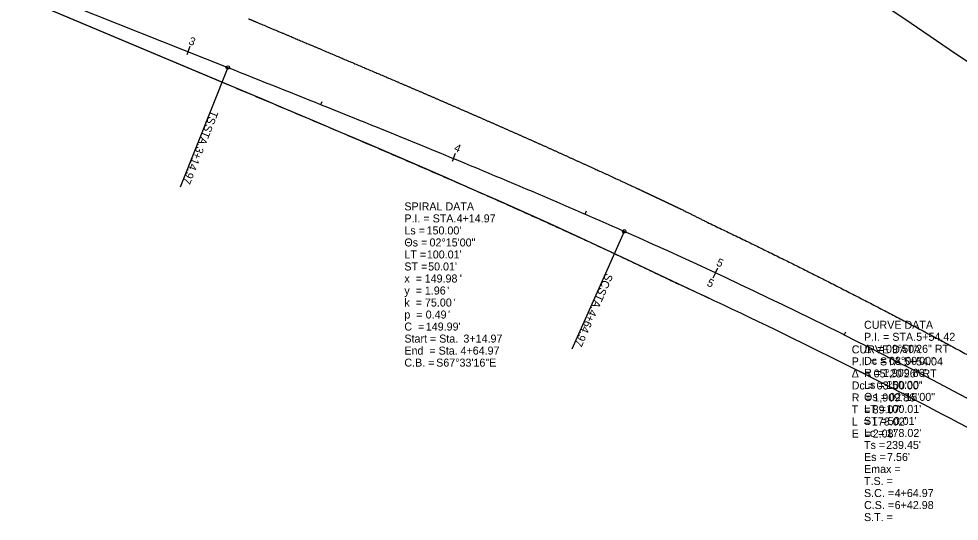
# Model space of a CAD drawing. Extents: x 1323137 to 1326838, y 458936 to 461644.
# Drawn here: x 1325220.9 to 1325549.7, y 459598.5 to 459774 of the extents above; entities that cross this region are included whole.
import ezdxf

# ---------------------------------------------------------------- set-up
doc = ezdxf.new("R2010")
doc.units = 0
for name, color, linetype in [('Default', 7, 'Continuous'), ('DT_P_Tie', 7, 'Continuous'), ('MD_P_ACB_B', 7, 'Continuous'), ('MD_P_ACSC_B', 7, 'Continuous'), ('MD_P_AGB_B', 7, 'Continuous'), ('MD_P_AGB_T', 7, 'Continuous'), ('PV_P_Shoulder', 7, 'Continuous'), ('SG_P_Conduit', 7, 'Continuous'), ('SG_P_Mast_Arm', 7, 'Continuous'), ('SN_P_Signs', 7, 'Continuous')]:
    doc.layers.add(name, color=color, linetype=linetype)

msp = doc.modelspace()

# ---------------------------------------------------------------- linework, layer by layer
at = {"layer": 'Default'}
msp.add_line((1325001.32, 459873.45), (1325293.97, 459757.01), dxfattribs=at)
for points in [[(1325451.7, 459681.24), (1325442.79, 459685.53), (1325433.79, 459689.8), (1325424.78, 459694.02), (1325415.73, 459698.2), (1325406.67, 459702.34), (1325397.58, 459706.44), (1325388.48, 459710.51), (1325379.35, 459714.54), (1325370.21, 459718.54), (1325361.06, 459722.52), (1325351.89, 459726.48), (1325342.71, 459730.41), (1325333.52, 459734.33), (1325324.32, 459738.24), (1325315.11, 459742.13), (1325305.9, 459746.02), (1325296.69, 459749.9), (1325222.91, 459780.98), (1325213.53, 459784.78), (1325076.26, 459836.24)], [(1325586.72, 459613.4), (1325584.96, 459614.34), (1325576.17, 459619), (1325567.35, 459623.63), (1325558.51, 459628.2), (1325549.7, 459632.7)]]:
    msp.add_lwpolyline(points, dxfattribs=at)
for centre, radius, start, end in [((1332431.06, 469929.07), 12277.67, 232.043309, 236.873031), ((1324657.44, 457954.27), 1909.86, 60.71386, 66.05442), ((1324657.44, 457954.27), 1900.86, 62.00488, 65.30182)]:
    msp.add_arc(centre, radius, start, end, dxfattribs=at)
msp.add_open_spline([(1325293.97, 459757.01), (1325305.58, 459752.39), (1325328.82, 459743.16), (1325363.59, 459729.11), (1325398.23, 459714.75), (1325421.17, 459704.82), (1325432.6, 459699.75)], degree=3, dxfattribs=at)
at = {"layer": 'DT_P_Tie'}
for p, q in [((1325038.48, 459858.66), (1325291.94, 459751.9)), ((1325038.48, 459858.66), (1325291.94, 459751.9)), ((1325439.3, 459713.73), (1325439.31, 459713.72)), ((1325439.3, 459713.73), (1325439.31, 459713.72)), ((1325439.31, 459713.72), (1325439.33, 459713.71)), ((1325439.31, 459713.72), (1325439.33, 459713.71)), ((1325462.05, 459702.73), (1325462.14, 459702.69)), ((1325462.05, 459702.73), (1325462.14, 459702.69))]:
    msp.add_line(p, q, dxfattribs=at)
msp.add_arc((1324657.44, 457954.27), 1900.86, 62.00341, 65.30341, dxfattribs=at)
msp.add_arc((1324657.44, 457954.27), 1900.86, 62.00341, 65.30341, dxfattribs=at)
for points, degree in [([(1325301.25, 459774.02), (1325302.56, 459773.47), (1325307.09, 459771.56), (1325315.35, 459768.09), (1325321.89, 459765.32), (1325328.9, 459762.36), (1325335.79, 459759.44), (1325342.71, 459756.5), (1325349.62, 459753.56), (1325356.54, 459750.6), (1325363.46, 459747.63), (1325370.37, 459744.64), (1325377.28, 459741.64), (1325384.2, 459738.63), (1325391.1, 459735.59), (1325398.01, 459732.54), (1325404.92, 459729.46), (1325411.78, 459726.37), (1325418.78, 459723.2), (1325425.29, 459720.23), (1325433.53, 459716.42), (1325438.02, 459714.32), (1325439.3, 459713.73)], 2), ([(1325301.25, 459774.02), (1325302.56, 459773.47), (1325307.09, 459771.56), (1325315.35, 459768.09), (1325321.89, 459765.32), (1325328.9, 459762.36), (1325335.79, 459759.44), (1325342.71, 459756.5), (1325349.62, 459753.56), (1325356.54, 459750.6), (1325363.46, 459747.63), (1325370.37, 459744.64), (1325377.28, 459741.64), (1325384.2, 459738.63), (1325391.1, 459735.59), (1325398.01, 459732.54), (1325404.92, 459729.46), (1325411.78, 459726.37), (1325418.78, 459723.2), (1325425.29, 459720.23), (1325433.53, 459716.42), (1325438.02, 459714.32), (1325439.3, 459713.73)], 2), ([(1325291.94, 459751.9), (1325294.24, 459750.93), (1325298.85, 459748.99), (1325305.76, 459746.08), (1325312.67, 459743.17), (1325319.58, 459740.25), (1325326.48, 459737.32), (1325333.38, 459734.39), (1325340.27, 459731.46), (1325347.16, 459728.51), (1325354.04, 459725.55), (1325360.91, 459722.59), (1325367.78, 459719.6), (1325374.64, 459716.61), (1325381.49, 459713.6), (1325388.34, 459710.57), (1325395.17, 459707.53), (1325401.99, 459704.46), (1325408.8, 459701.38), (1325415.59, 459698.27), (1325422.38, 459695.14), (1325426.89, 459693.03), (1325429.15, 459691.98)], 3), ([(1325291.94, 459751.9), (1325294.24, 459750.93), (1325298.85, 459748.99), (1325305.76, 459746.08), (1325312.67, 459743.17), (1325319.58, 459740.25), (1325326.48, 459737.32), (1325333.38, 459734.39), (1325340.27, 459731.46), (1325347.16, 459728.51), (1325354.04, 459725.55), (1325360.91, 459722.59), (1325367.78, 459719.6), (1325374.64, 459716.61), (1325381.49, 459713.6), (1325388.34, 459710.57), (1325395.17, 459707.53), (1325401.99, 459704.46), (1325408.8, 459701.38), (1325415.59, 459698.27), (1325422.38, 459695.14), (1325426.89, 459693.03), (1325429.15, 459691.98)], 3), ([(1325439.33, 459713.71), (1325439.54, 459713.61), (1325440.26, 459713.28), (1325441.59, 459712.65), (1325442.64, 459712.16), (1325443.77, 459711.63), (1325444.88, 459711.1), (1325445.99, 459710.58), (1325447.1, 459710.05), (1325448.2, 459709.53), (1325449.32, 459709), (1325450.37, 459708.5), (1325451.7, 459707.87), (1325452.42, 459707.52), (1325452.63, 459707.42)], 2), ([(1325439.33, 459713.71), (1325439.54, 459713.61), (1325440.26, 459713.28), (1325441.59, 459712.65), (1325442.64, 459712.16), (1325443.77, 459711.63), (1325444.88, 459711.1), (1325445.99, 459710.58), (1325447.1, 459710.05), (1325448.2, 459709.53), (1325449.32, 459709), (1325450.37, 459708.5), (1325451.7, 459707.87), (1325452.42, 459707.52), (1325452.63, 459707.42)], 2), ([(1325452.38, 459707.54), (1325452.59, 459707.44), (1325453.29, 459707.09), (1325454.58, 459706.45), (1325455.6, 459705.95), (1325456.69, 459705.41), (1325457.75, 459704.88), (1325458.84, 459704.33), (1325459.86, 459703.83), (1325461.15, 459703.18), (1325461.85, 459702.83), (1325462.05, 459702.73)], 3), ([(1325452.38, 459707.54), (1325452.59, 459707.44), (1325453.29, 459707.09), (1325454.58, 459706.45), (1325455.6, 459705.95), (1325456.69, 459705.41), (1325457.75, 459704.88), (1325458.84, 459704.33), (1325459.86, 459703.83), (1325461.15, 459703.18), (1325461.85, 459702.83), (1325462.05, 459702.73)], 3), ([(1325461.62, 459702.94), (1325463.28, 459702.14), (1325466.62, 459700.55), (1325471.61, 459698.15), (1325476.6, 459695.73), (1325481.58, 459693.3), (1325486.56, 459690.85), (1325491.52, 459688.39), (1325496.48, 459685.91), (1325501.43, 459683.42), (1325506.37, 459680.92), (1325511.31, 459678.4), (1325516.24, 459675.87), (1325521.16, 459673.33), (1325526.08, 459670.77), (1325530.98, 459668.19), (1325535.88, 459665.61), (1325540.77, 459663), (1325545.66, 459660.39), (1325550.53, 459657.76), (1325555.4, 459655.12), (1325558.64, 459653.34), (1325560.26, 459652.46)], 3), ([(1325461.62, 459702.94), (1325463.28, 459702.14), (1325466.62, 459700.55), (1325471.61, 459698.15), (1325476.6, 459695.73), (1325481.58, 459693.3), (1325486.56, 459690.85), (1325491.52, 459688.39), (1325496.48, 459685.91), (1325501.43, 459683.42), (1325506.37, 459680.92), (1325511.31, 459678.4), (1325516.24, 459675.87), (1325521.16, 459673.33), (1325526.08, 459670.77), (1325530.98, 459668.19), (1325535.88, 459665.61), (1325540.77, 459663), (1325545.66, 459660.39), (1325550.53, 459657.76), (1325555.4, 459655.12), (1325558.64, 459653.34), (1325560.26, 459652.46)], 3), ([(1325429.15, 459691.98), (1325429.52, 459691.8), (1325430.28, 459691.45), (1325431.4, 459690.92), (1325432.53, 459690.39), (1325433.66, 459689.86), (1325434.79, 459689.33), (1325435.91, 459688.79), (1325437.04, 459688.26), (1325438.17, 459687.73), (1325439.29, 459687.19), (1325440.42, 459686.66), (1325441.54, 459686.12), (1325442.67, 459685.58), (1325443.79, 459685.05), (1325444.91, 459684.51), (1325446.04, 459683.97), (1325447.16, 459683.43), (1325448.28, 459682.89), (1325449.4, 459682.35), (1325450.53, 459681.8), (1325451.27, 459681.44), (1325451.65, 459681.26)], 3), ([(1325429.15, 459691.98), (1325429.52, 459691.8), (1325430.28, 459691.45), (1325431.4, 459690.92), (1325432.53, 459690.39), (1325433.66, 459689.86), (1325434.79, 459689.33), (1325435.91, 459688.79), (1325437.04, 459688.26), (1325438.17, 459687.73), (1325439.29, 459687.19), (1325440.42, 459686.66), (1325441.54, 459686.12), (1325442.67, 459685.58), (1325443.79, 459685.05), (1325444.91, 459684.51), (1325446.04, 459683.97), (1325447.16, 459683.43), (1325448.28, 459682.89), (1325449.4, 459682.35), (1325450.53, 459681.8), (1325451.27, 459681.44), (1325451.65, 459681.26)], 3)]:
    msp.add_open_spline(points, degree=degree, dxfattribs=at)
at = {"layer": 'MD_P_ACB_B'}
for p, q in [((1325293.97, 459757.01), (1325277.33, 459715.2)), ((1325432.6, 459699.75), (1325414.33, 459658.62))]:
    msp.add_line(p, q, dxfattribs=at)
for centre in [(1325293.97, 459757.01), (1325432.6, 459699.75)]:
    msp.add_circle(centre, 0.6, dxfattribs=at)
at = {"layer": 'MD_P_ACSC_B'}
for p, q in [((1325293.97, 459757.01), (1325277.33, 459715.2)), ((1325432.6, 459699.75), (1325414.33, 459658.62))]:
    msp.add_line(p, q, dxfattribs=at)
for centre in [(1325293.97, 459757.01), (1325432.6, 459699.75)]:
    msp.add_circle(centre, 0.6, dxfattribs=at)
at = {"layer": 'PV_P_Shoulder'}
for p, q in [((1325280.06, 459762.55), (1325279.62, 459761.43)), ((1325372.85, 459725.25), (1325372.39, 459724.14)), ((1325464.48, 459685.24), (1325463.64, 459683.42))]:
    msp.add_line(p, q, dxfattribs=at)
at = {"layer": 'SG_P_Conduit'}
msp.add_line((1325001.32, 459873.45), (1325293.97, 459757.01), dxfattribs=at)
msp.add_arc((1324657.44, 457954.27), 1909.86, 60.71386, 66.05442, dxfattribs=at)
msp.add_open_spline([(1325293.97, 459757.01), (1325305.58, 459752.39), (1325328.82, 459743.16), (1325363.59, 459729.11), (1325398.23, 459714.75), (1325421.17, 459704.82), (1325432.6, 459699.75)], degree=3, dxfattribs=at)
at = {"layer": 'SG_P_Mast_Arm'}
for p, q in [((1325280.06, 459762.55), (1325280.8, 459764.41)), ((1325326.51, 459744.04), (1325326.96, 459745.15)), ((1325372.85, 459725.25), (1325373.61, 459727.1)), ((1325418.9, 459705.77), (1325419.37, 459706.87)), ((1325464.48, 459685.24), (1325465.33, 459687.05)), ((1325509.52, 459663.52), (1325510.05, 459664.59))]:
    msp.add_line(p, q, dxfattribs=at)
at = {"layer": 'SN_P_Signs'}
msp.add_line((1325001.32, 459873.45), (1325293.97, 459757.01), dxfattribs=at)
for centre, radius, start, end in [((1332431.06, 469929.07), 12277.67, 232.043309, 236.873031), ((1324657.44, 457954.27), 1909.86, 60.71386, 66.05442)]:
    msp.add_arc(centre, radius, start, end, dxfattribs=at)
msp.add_open_spline([(1325293.97, 459757.01), (1325305.58, 459752.39), (1325328.82, 459743.16), (1325363.59, 459729.11), (1325398.23, 459714.75), (1325421.17, 459704.82), (1325432.6, 459699.75)], degree=3, dxfattribs=at)

# ---------------------------------------------------------------- texts
at = {"layer": 'MD_P_ACB_B'}
for s, rotation, p in [('TS', 248.3044, (1325288.13, 459742.23)), (' STA. ', 248.3044, (1325286.6, 459738.38)), ('3+14.97', 248.3044, (1325283.11, 459729.6)), ('SC', 246.0544, (1325426.22, 459685.28)), (' STA. ', 246.0544, (1325424.47, 459681.34)), ('4+64.97', 246.0544, (1325420.63, 459672.71))]:
    msp.add_text(s, height=2.8, rotation=rotation, dxfattribs=at).set_placement(p)
at = {"layer": 'MD_P_ACSC_B'}
for s, rotation, p in [('TS', 248.3044, (1325288.13, 459742.23)), (' STA. ', 248.3044, (1325286.6, 459738.38)), ('3+14.97', 248.3044, (1325283.11, 459729.6)), ('SC', 246.0544, (1325426.22, 459685.28)), (' STA. ', 246.0544, (1325424.47, 459681.34)), ('4+64.97', 246.0544, (1325420.63, 459672.71))]:
    msp.add_text(s, height=2.8, rotation=rotation, dxfattribs=at).set_placement(p)
at = {"layer": 'MD_P_AGB_B'}
for s, p in [('SPIRAL DATA', (1325355.71, 459707.07)), ('P.I. = STA. ', (1325355.71, 459702.87)), ('4+14.97', (1325373.97, 459702.87)), ('Ls = ', (1325355.71, 459698.67)), ("150.00'", (1325363.47, 459698.67)), ('Θs = ', (1325355.71, 459694.47)), ('02°15\'00"', (1325364.51, 459694.47)), ('LT = ', (1325355.71, 459690.27)), ("100.01'", (1325363.56, 459690.27)), ('ST = ', (1325355.71, 459686.07)), ("50.01'", (1325364.02, 459686.07)), ('x  = ', (1325355.71, 459681.87)), ('149.98', (1325362.81, 459681.87)), ("'", (1325375.09, 459681.87)), ('y  = ', (1325355.71, 459677.67)), ('1.96', (1325362.87, 459677.67)), ("'", (1325370.69, 459677.67)), ('k  = ', (1325355.71, 459673.47)), ('75.00', (1325362.9, 459673.47)), ("'", (1325372.95, 459673.47)), ('p  = ', (1325355.71, 459669.27)), ('0.49', (1325363.16, 459669.27)), ("'", (1325370.98, 459669.27)), ('C  = ', (1325355.71, 459665.07)), ("149.99'", (1325363.2, 459665.07)), ('CURVE DATA', (1325516.46, 459665.69)), ('Start = Sta. ', (1325355.71, 459660.87)), ('3+14.97', (1325376.36, 459660.87)), ('P.I. = STA. ', (1325516.46, 459661.49)), ('5+54.42', (1325534.73, 459661.49)), ('End  = Sta. ', (1325355.71, 459656.67)), ('4+64.97', (1325375.34, 459656.67)), ('CURVE DATA', (1325512.15, 459657.09)), ('Δ  = ', (1325516.46, 459657.29)), ('09°50\'26" RT', (1325524.14, 459657.29)), ('C.B. = ', (1325355.71, 459652.47)), ('S67°33\'16"E', (1325366.83, 459652.47)), ('P.I. = STA. ', (1325512.15, 459652.89)), ('Dc = ', (1325516.46, 459653.09)), ('03°00\'00"', (1325525.2, 459653.09)), ('5+54.04', (1325530.41, 459652.89)), ('Δ  = ', (1325512.15, 459648.69)), ('R = ', (1325516.46, 459648.89)), ('05°20\'26" RT', (1325519.82, 459648.69)), ("1,909.86'", (1325523.05, 459648.89)), ('Dc = ', (1325512.15, 459644.49)), ('Ls = ', (1325516.46, 459644.69)), ('03°00\'00"', (1325520.88, 459644.49)), ("150.00'", (1325524.22, 459644.69)), ('R  = ', (1325512.15, 459640.29)), ('Θs = ', (1325516.46, 459640.49)), ("1,909.86'", (1325519.73, 459640.29)), ('02°15\'00"', (1325525.26, 459640.49)), ('T  = ', (1325512.15, 459636.09)), ('LT = ', (1325516.46, 459636.29)), ("89.07'", (1325519.48, 459636.09)), ("100.01'", (1325524.31, 459636.29)), ('L  = ', (1325512.15, 459631.89)), ('ST = ', (1325516.46, 459632.09)), ("178.02'", (1325519.19, 459631.89)), ("50.01'", (1325524.77, 459632.09)), ('E  = ', (1325512.15, 459627.69)), ('Lc = ', (1325516.46, 459627.89)), ("2.08'", (1325519.49, 459627.69)), ("178.02'", (1325524.34, 459627.89)), ('Ts = ', (1325516.46, 459623.69)), ("239.45'", (1325524.19, 459623.69)), ('Es = ', (1325516.46, 459619.49)), ("7.56'", (1325524.52, 459619.49)), ('Emax = ', (1325516.46, 459615.29)), ('T.S. = ', (1325516.46, 459611.09)), ('S.C. = ', (1325516.46, 459606.89)), ('4+64.97', (1325527.18, 459606.89)), ('C.S. = ', (1325516.46, 459602.69)), ('6+42.98', (1325527.18, 459602.69)), ('S.T. = ', (1325516.46, 459598.49))]:
    msp.add_text(s, height=2.8, dxfattribs=at).set_placement(p)
at = {"layer": 'MD_P_AGB_T'}
for s, p in [('SPIRAL DATA', (1325355.71, 459707.07)), ('P.I. = STA. ', (1325355.71, 459702.87)), ('4+14.97', (1325373.97, 459702.87)), ('Ls = ', (1325355.71, 459698.67)), ("150.00'", (1325363.47, 459698.67)), ('Θs = ', (1325355.71, 459694.47)), ('02°15\'00"', (1325364.51, 459694.47)), ('LT = ', (1325355.71, 459690.27)), ("100.01'", (1325363.56, 459690.27)), ('ST = ', (1325355.71, 459686.07)), ("50.01'", (1325364.02, 459686.07)), ('x  = ', (1325355.71, 459681.87)), ('149.98', (1325362.81, 459681.87)), ("'", (1325375.09, 459681.87)), ('y  = ', (1325355.71, 459677.67)), ('1.96', (1325362.87, 459677.67)), ("'", (1325370.69, 459677.67)), ('k  = ', (1325355.71, 459673.47)), ('75.00', (1325362.9, 459673.47)), ("'", (1325372.95, 459673.47)), ('p  = ', (1325355.71, 459669.27)), ('0.49', (1325363.16, 459669.27)), ("'", (1325370.98, 459669.27)), ('C  = ', (1325355.71, 459665.07)), ("149.99'", (1325363.2, 459665.07)), ('CURVE DATA', (1325516.46, 459665.69)), ('Start = Sta. ', (1325355.71, 459660.87)), ('3+14.97', (1325376.36, 459660.87)), ('P.I. = STA. ', (1325516.46, 459661.49)), ('5+54.42', (1325534.73, 459661.49)), ('End  = Sta. ', (1325355.71, 459656.67)), ('4+64.97', (1325375.34, 459656.67)), ('CURVE DATA', (1325512.15, 459657.09)), ('Δ  = ', (1325516.46, 459657.29)), ('09°50\'26" RT', (1325524.14, 459657.29)), ('C.B. = ', (1325355.71, 459652.47)), ('S67°33\'16"E', (1325366.83, 459652.47)), ('P.I. = STA. ', (1325512.15, 459652.89)), ('Dc = ', (1325516.46, 459653.09)), ('03°00\'00"', (1325525.2, 459653.09)), ('5+54.04', (1325530.41, 459652.89)), ('Δ  = ', (1325512.15, 459648.69)), ('R = ', (1325516.46, 459648.89)), ('05°20\'26" RT', (1325519.82, 459648.69)), ("1,909.86'", (1325523.05, 459648.89)), ('Dc = ', (1325512.15, 459644.49)), ('Ls = ', (1325516.46, 459644.69)), ('03°00\'00"', (1325520.88, 459644.49)), ("150.00'", (1325524.22, 459644.69)), ('R  = ', (1325512.15, 459640.29)), ('Θs = ', (1325516.46, 459640.49)), ("1,909.86'", (1325519.73, 459640.29)), ('02°15\'00"', (1325525.26, 459640.49)), ('T  = ', (1325512.15, 459636.09)), ('LT = ', (1325516.46, 459636.29)), ("89.07'", (1325519.48, 459636.09)), ("100.01'", (1325524.31, 459636.29)), ('L  = ', (1325512.15, 459631.89)), ('ST = ', (1325516.46, 459632.09)), ("178.02'", (1325519.19, 459631.89)), ("50.01'", (1325524.77, 459632.09)), ('E  = ', (1325512.15, 459627.69)), ('Lc = ', (1325516.46, 459627.89)), ("2.08'", (1325519.49, 459627.69)), ("178.02'", (1325524.34, 459627.89)), ('Ts = ', (1325516.46, 459623.69)), ("239.45'", (1325524.19, 459623.69)), ('Es = ', (1325516.46, 459619.49)), ("7.56'", (1325524.52, 459619.49)), ('Emax = ', (1325516.46, 459615.29)), ('T.S. = ', (1325516.46, 459611.09)), ('S.C. = ', (1325516.46, 459606.89)), ('4+64.97', (1325527.18, 459606.89)), ('C.S. = ', (1325516.46, 459602.69)), ('6+42.98', (1325527.18, 459602.69)), ('S.T. = ', (1325516.46, 459598.49))]:
    msp.add_text(s, height=2.8, dxfattribs=at).set_placement(p)
at = {"layer": 'PV_P_Shoulder'}
msp.add_text('5', height=2.8, rotation=335.0034, dxfattribs=at).set_placement((1325461.27, 459680.88))
at = {"layer": 'SG_P_Mast_Arm'}
for s, rotation, p in [('3', 338.3044, (1325280.02, 459765.25)), ('4', 337.5813, (1325372.84, 459727.95)), ('5', 335.0034, (1325464.57, 459687.95))]:
    msp.add_text(s, height=2.8, rotation=rotation, dxfattribs=at).set_placement(p)

doc.saveas('drawing.dxf')
